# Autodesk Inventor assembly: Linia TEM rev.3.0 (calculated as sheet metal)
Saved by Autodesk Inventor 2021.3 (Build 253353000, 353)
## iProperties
Created: 2023-02
Part Number: Linia TEM rev.3.0 (calculated as sheet metal)
Document SubType Name: Assembly
Designer: AdminForWorker
Title: Linia TEM rev.3.0 (calculated as sheet metal) v9
Author: AdminForWorker
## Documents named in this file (3)
- z:\worker\convert-fusion-r08-cosv3\tmp\job-1\107\output\files\3be6c370-91f6-42f5-af7d-0ff419ee254f\ba991f34-4133-484e-8d76-1a6c3428255e.iam
- z:\worker\convert-fusion-r08-cosv3\tmp\job-1\107\output\files\3be6c370-91f6-42f5-af7d-0ff419ee254f\bok.ipt
- z:\worker\convert-fusion-r08-cosv3\tmp\job-1\107\output\files\3be6c370-91f6-42f5-af7d-0ff419ee254f\srodek.ipt
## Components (3 placed, 2 different names)
1. bok:1
2. bok:2
3. srodek:1
